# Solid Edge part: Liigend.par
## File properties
Author: Türk
Template: Iso Part.par
Last saved by: Türk
Revision: 10
Application: Solid Edge
Accuracy: 0,990
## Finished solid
Body 1: solid body, 13 faces, 28 edges, 16 vertices.
  Faces by surface: plane 8, cylinder 5
  Edges by curve: line 16, circle 12
Bounding box of the edges (mm): 20.000 x 20.000 x 110.000, from (-10, -10, -100) to (10, 10, 10).
Cylindrical faces by radius (mm): R5 x2, R6 x1, R10 x2
Planar faces by outward normal: +x 2, +y 2, -x 2, -y 2
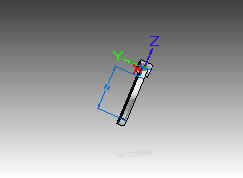
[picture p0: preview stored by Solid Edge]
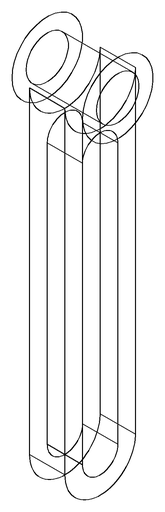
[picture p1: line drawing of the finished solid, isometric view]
